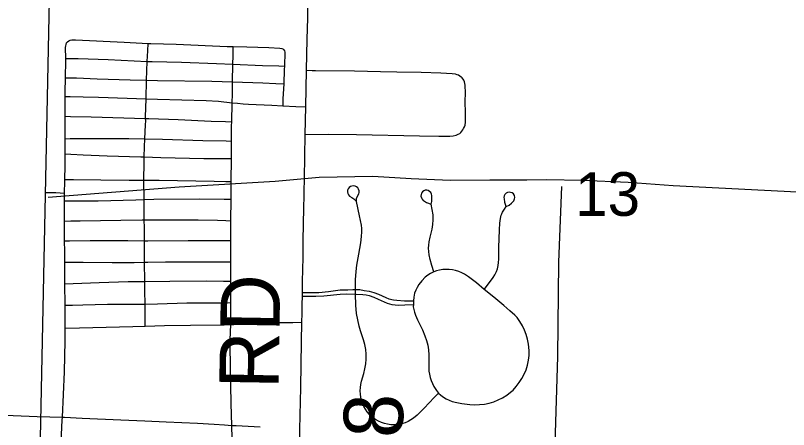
# Model space of a CAD drawing. Extents: x -59 to 43, y 0 to 22.
# Drawn here: x 24.177 to 24.918, y 18.594 to 18.99 of the extents above; entities that cross this region are included whole.
import ezdxf

# ---------------------------------------------------------------- set-up
doc = ezdxf.new("R2010")
doc.units = 0
for name, color, linetype in [('Default', 7, 'Continuous'), ('GM_X_City_Street', 7, 'Continuous'), ('GM_X_Minor_River', 7, 'Continuous'), ('GM_X_Section', 7, 'Continuous'), ('GM_X_Section_Text', 7, 'Continuous'), ('GM_X_Township_Road', 7, 'Continuous'), ('GM_X_Township_Road_Text', 7, 'Continuous')]:
    doc.layers.add(name, color=color, linetype=linetype)

msp = doc.modelspace()

# ---------------------------------------------------------------- linework, layer by layer
at = {"layer": 'Default'}
msp.add_lwpolyline([(23.51667, 19.36712), (23.51667, 18.36457), (24.19635, 18.35229), (24.21701, 19.34715)], close=True, dxfattribs=at)
at = {"layer": 'GM_X_City_Street'}
for p, q in [((24.50302, 18.72348), (24.50306, 18.72775)), ((24.55855, 18.717), (24.55845, 18.71346))]:
    msp.add_line(p, q, dxfattribs=at)
for points in [[(24.45614, 18.93773), (24.46159, 18.93762), (24.46471, 18.93756), (24.5021, 18.93711), (24.52702, 18.93654), (24.54259, 18.93626), (24.56597, 18.93586), (24.58467, 18.93531), (24.59555, 18.93469), (24.59863, 18.93429), (24.60013, 18.93389), (24.60157, 18.93334), (24.60292, 18.93257), (24.60416, 18.93162), (24.60525, 18.93051)], [(24.60285, 18.87732), (24.60401, 18.87834), (24.60505, 18.87947), (24.60592, 18.88073), (24.60659, 18.88211), (24.60738, 18.8835), (24.60812, 18.88523), (24.60836, 18.88807), (24.60836, 18.89288), (24.60836, 18.89831), (24.60823, 18.90657), (24.60836, 18.91741), (24.60823, 18.92202), (24.60813, 18.92355), (24.60789, 18.92506), (24.60761, 18.92676), (24.60686, 18.92824), (24.60525, 18.93051)], [(24.45481, 18.87638), (24.47765, 18.87661), (24.50393, 18.87612), (24.56419, 18.87512), (24.58273, 18.87471), (24.59355, 18.87464), (24.59662, 18.87484), (24.59961, 18.8756), (24.60134, 18.87646), (24.60285, 18.87732)], [(24.50306, 18.72775), (24.50309, 18.73252), (24.50312, 18.73717), (24.50365, 18.74489), (24.50436, 18.75103), (24.50638, 18.76167), (24.50827, 18.77234), (24.50894, 18.77849), (24.50922, 18.78312), (24.50908, 18.78622), (24.50865, 18.78928), (24.50673, 18.79836), (24.50399, 18.81203), (24.50392, 18.81358), (24.50411, 18.8151), (24.5046, 18.81656), (24.50608, 18.81929), (24.50655, 18.82075), (24.50655, 18.82229), (24.50607, 18.82375), (24.50522, 18.82505), (24.50409, 18.82609), (24.50269, 18.82675), (24.50117, 18.82702), (24.49962, 18.82689), (24.49817, 18.82637), (24.49693, 18.82547), (24.49598, 18.82424), (24.49541, 18.8228), (24.49528, 18.82127), (24.49562, 18.81979), (24.49639, 18.81845), (24.49744, 18.8173), (24.49968, 18.81607), (24.50145, 18.81476), (24.50269, 18.81336), (24.50359, 18.81238)], [(24.57806, 18.7448), (24.57628, 18.75069), (24.57451, 18.7566), (24.57361, 18.76115), (24.57323, 18.76421), (24.57311, 18.76729), (24.57326, 18.77036), (24.5736, 18.77343), (24.57454, 18.77797), (24.57633, 18.78547), (24.57709, 18.79004), (24.57753, 18.79465), (24.57752, 18.79928), (24.57556, 18.80969), (24.57608, 18.81221), (24.57631, 18.81579), (24.57623, 18.81777), (24.57579, 18.81926), (24.57507, 18.82063), (24.57406, 18.82179), (24.57279, 18.82262), (24.57132, 18.82301), (24.56981, 18.82295), (24.56838, 18.82241), (24.56717, 18.82147), (24.56628, 18.82021), (24.56579, 18.81875), (24.56574, 18.81722), (24.56611, 18.81573), (24.56683, 18.81436), (24.56785, 18.8132), (24.56906, 18.81226), (24.57119, 18.81111), (24.57541, 18.80964)], [(24.62643, 18.72789), (24.62937, 18.73187), (24.63492, 18.7394), (24.63653, 18.74199), (24.63825, 18.74496), (24.63911, 18.74755), (24.63985, 18.75063), (24.6401, 18.75371), (24.64023, 18.75694), (24.6405, 18.76787), (24.64083, 18.78503), (24.6412, 18.79126), (24.64183, 18.7959), (24.64266, 18.7989), (24.64325, 18.80034), (24.64395, 18.80173), (24.64574, 18.80461), (24.64752, 18.80728), (24.65012, 18.80869), (24.65257, 18.81065), (24.65384, 18.8117), (24.65486, 18.8128), (24.65549, 18.81454), (24.65557, 18.81607), (24.6554, 18.81798), (24.65447, 18.81954), (24.65307, 18.82044), (24.65167, 18.82086), (24.65012, 18.82107), (24.64859, 18.82079), (24.64723, 18.82006), (24.64617, 18.81895), (24.64556, 18.8176), (24.64526, 18.81607), (24.64531, 18.8145), (24.64589, 18.81139), (24.64718, 18.80749)], [(24.57806, 18.7448), (24.57485, 18.74326), (24.57228, 18.74152), (24.56991, 18.7395), (24.5667, 18.73612), (24.56381, 18.73246), (24.5621, 18.72986), (24.56068, 18.7271), (24.55967, 18.72417), (24.55884, 18.7205), (24.55855, 18.717)], [(24.62643, 18.72789), (24.61882, 18.73414), (24.61141, 18.73979), (24.60755, 18.74242), (24.60482, 18.74389), (24.60195, 18.74509), (24.59899, 18.74603), (24.59595, 18.74667), (24.59286, 18.74702), (24.58975, 18.74709), (24.58665, 18.74688), (24.58357, 18.74641), (24.58055, 18.74567), (24.57806, 18.7448)], [(24.45219, 18.72137), (24.46021, 18.72134), (24.4649, 18.72132), (24.47269, 18.72175), (24.48822, 18.72341), (24.49445, 18.72367), (24.50302, 18.72348)], [(24.45225, 18.72501), (24.45985, 18.72501), (24.46807, 18.72502), (24.47711, 18.72584), (24.4883, 18.72733), (24.49554, 18.7275), (24.50064, 18.72767), (24.50306, 18.72775)], [(24.50302, 18.72348), (24.50382, 18.72346), (24.51006, 18.72306), (24.51315, 18.72266), (24.5162, 18.722), (24.52064, 18.72056), (24.5249, 18.71862), (24.53053, 18.71589), (24.53345, 18.71476), (24.53793, 18.7135), (24.54101, 18.71306), (24.54413, 18.71295), (24.55038, 18.71317), (24.55845, 18.71346)], [(24.58267, 18.62863), (24.5785, 18.62425), (24.56888, 18.61413), (24.56227, 18.60757), (24.55873, 18.60455), (24.55617, 18.60281), (24.55341, 18.60139), (24.55053, 18.60023), (24.54609, 18.59884), (24.54305, 18.59823), (24.53996, 18.59801), (24.53686, 18.59822), (24.5338, 18.59872), (24.53079, 18.59948), (24.52785, 18.60048), (24.52501, 18.60173), (24.52229, 18.60322), (24.51978, 18.60503), (24.51636, 18.60819), (24.51433, 18.61054), (24.51256, 18.61308), (24.51103, 18.61579), (24.50978, 18.61863), (24.50881, 18.62157), (24.50812, 18.6246), (24.50771, 18.62767), (24.50756, 18.63078), (24.50768, 18.63388), (24.50806, 18.63696), (24.50869, 18.63999), (24.51097, 18.64741), (24.51208, 18.65193), (24.51285, 18.65652), (24.51325, 18.66115), (24.51323, 18.66581), (24.51286, 18.67045), (24.51205, 18.67503), (24.51081, 18.67952), (24.50778, 18.68832), (24.50653, 18.6928), (24.50514, 18.69884), (24.50406, 18.70495), (24.50322, 18.71267), (24.50302, 18.72348)], [(24.50306, 18.72775), (24.50705, 18.72767), (24.51146, 18.727), (24.51606, 18.72624), (24.52056, 18.72501), (24.52492, 18.72334), (24.532, 18.72008), (24.53492, 18.71901), (24.53945, 18.71794), (24.54253, 18.71754), (24.54999, 18.71683), (24.55855, 18.717)], [(24.58267, 18.62863), (24.58482, 18.62646), (24.58726, 18.62454), (24.58992, 18.62294), (24.59275, 18.62165), (24.59568, 18.62063), (24.6002, 18.61947), (24.60479, 18.61868), (24.6125, 18.6177), (24.61716, 18.61745), (24.62182, 18.61753), (24.62647, 18.61793), (24.63104, 18.6188), (24.63549, 18.62018), (24.63978, 18.62203), (24.64391, 18.62419), (24.6479, 18.6266), (24.65165, 18.62937), (24.65392, 18.63149), (24.65699, 18.63499), (24.65978, 18.63873), (24.66234, 18.64263), (24.66459, 18.64671), (24.66645, 18.65099), (24.66787, 18.65542), (24.66882, 18.65999), (24.66928, 18.66463), (24.66927, 18.66929), (24.66869, 18.67548), (24.66793, 18.68008), (24.66667, 18.68457), (24.66502, 18.68893), (24.66298, 18.69312), (24.66055, 18.69709), (24.65781, 18.70087), (24.65573, 18.70317), (24.65104, 18.70725), (24.64518, 18.71235), (24.63564, 18.72033), (24.62643, 18.72789)], [(24.55845, 18.71346), (24.55839, 18.71124), (24.55958, 18.70612), (24.56054, 18.70318), (24.56231, 18.69886), (24.56714, 18.68911), (24.56957, 18.68339), (24.57109, 18.67897), (24.57226, 18.67447), (24.57302, 18.66987), (24.57334, 18.66522), (24.57317, 18.65434), (24.57339, 18.64968), (24.57382, 18.64661), (24.57453, 18.64358), (24.5755, 18.64063), (24.57672, 18.63777), (24.57817, 18.63502), (24.5807, 18.6311), (24.58267, 18.62863)], [(24.12929, 18.60491), (24.13438, 18.60677), (24.1372, 18.60746), (24.1396, 18.60768), (24.14328, 18.60776), (24.15755, 18.60742), (24.17497, 18.60705), (24.19053, 18.60653), (24.1982, 18.60631)]]:
    msp.add_lwpolyline(points, dxfattribs=at)
at = {"layer": 'GM_X_Minor_River'}
for points in [[(24.20849, 18.81635), (24.33425, 18.82615), (24.42616, 18.83164), (24.46835, 18.83541), (24.51958, 18.83635), (24.55634, 18.83414), (24.59387, 18.83268), (24.63181, 18.83272), (24.66709, 18.83282), (24.68644, 18.83322), (24.71982, 18.83259), (24.76417, 18.83062), (24.80736, 18.82753), (24.89491, 18.82285), (24.97601, 18.81867), (25.02985, 18.8169), (25.09316, 18.81419), (25.14655, 18.80901), (25.1693, 18.8082)], [(24.70035, 18.8265), (24.69746, 18.75395), (24.6965, 18.66351), (24.69414, 18.57955)]]:
    msp.add_lwpolyline(points, dxfattribs=at)
at = {"layer": 'GM_X_Section'}
msp.add_lwpolyline([(24.21701, 19.34715), (25.1966, 19.31798), (25.19616, 19.28425), (25.1906, 18.3142), (24.19635, 18.35229)], close=True, dxfattribs=at)
at = {"layer": 'GM_X_Township_Road'}
for p, q in [((24.45614, 18.93773), (24.45678, 18.96768)), ((24.30281, 18.92824), (24.30358, 18.94625)), ((24.3853, 18.92671), (24.38559, 18.94372)), ((24.45538, 18.90269), (24.45614, 18.93773)), ((24.30235, 18.91045), (24.30281, 18.92824)), ((24.38446, 18.88843), (24.3849, 18.90669)), ((24.45481, 18.87638), (24.45538, 18.90269)), ((24.38397, 18.83111), (24.38415, 18.85328)), ((24.30058, 18.81402), (24.30032, 18.83258)), ((24.38383, 18.81435), (24.38397, 18.83111)), ((24.38369, 18.79361), (24.38383, 18.81435)), ((24.22441, 18.77452), (24.22431, 18.7934)), ((24.30105, 18.75399), (24.30087, 18.77457)), ((24.3012, 18.7356), (24.30105, 18.75399)), ((24.22479, 18.71277), (24.22474, 18.73325)), ((24.38362, 18.7152), (24.38359, 18.73581)), ((24.45219, 18.72137), (24.45225, 18.72501)), ((24.1982, 18.60631), (24.22225, 18.60563))]:
    msp.add_line(p, q, dxfattribs=at)
for points in [[(24.45678, 18.96768), (24.45722, 18.9876), (24.45775, 19.01167), (24.45839, 19.03959), (24.45899, 19.06286), (24.45942, 19.0797)], [(24.22541, 18.94915), (24.2253, 18.9596), (24.22547, 18.96111), (24.22572, 18.96259), (24.2263, 18.96398), (24.22712, 18.96514), (24.22827, 18.96588), (24.22966, 18.96654), (24.23114, 18.96679), (24.23494, 18.96682), (24.28151, 18.96463), (24.30433, 18.96349)], [(24.30358, 18.94625), (24.30402, 18.9564), (24.30433, 18.96349)], [(24.30433, 18.96349), (24.30695, 18.96336), (24.33118, 18.96265), (24.38024, 18.96054), (24.38588, 18.96041)], [(24.38559, 18.94372), (24.38573, 18.9515), (24.38588, 18.96041)], [(24.38588, 18.96041), (24.39888, 18.96011), (24.42, 18.95959), (24.43058, 18.95904), (24.43242, 18.95872), (24.43357, 18.95824), (24.43451, 18.9575), (24.43507, 18.95644), (24.43524, 18.95522), (24.43493, 18.94179)], [(24.22521, 18.9306), (24.22543, 18.94715), (24.22541, 18.94915)], [(24.22541, 18.94915), (24.23178, 18.94905), (24.23738, 18.94896), (24.266, 18.94795), (24.30358, 18.94625)], [(24.30358, 18.94625), (24.30829, 18.94604), (24.3363, 18.94541), (24.3699, 18.94442), (24.38559, 18.94372)], [(24.38559, 18.94372), (24.41406, 18.94244), (24.42962, 18.94196), (24.43493, 18.94179)], [(24.43493, 18.94179), (24.43485, 18.93842), (24.43423, 18.92494)], [(24.22502, 18.91267), (24.22502, 18.91666), (24.22521, 18.9306)], [(24.22521, 18.9306), (24.22887, 18.93059), (24.23569, 18.93055), (24.25554, 18.92971), (24.28719, 18.92874), (24.30281, 18.92824)], [(24.30281, 18.92824), (24.31325, 18.92791), (24.36538, 18.92731), (24.3853, 18.92671)], [(24.3849, 18.90669), (24.38509, 18.91487), (24.3853, 18.92671)], [(24.3853, 18.92671), (24.4144, 18.92583), (24.42681, 18.92527), (24.43423, 18.92494)], [(24.43423, 18.92494), (24.43357, 18.91048), (24.43327, 18.90379)], [(24.22489, 18.89373), (24.225, 18.89986), (24.22502, 18.91267)], [(24.22502, 18.91267), (24.22956, 18.91262), (24.242, 18.91247), (24.25692, 18.91191), (24.30235, 18.91045)], [(24.30199, 18.89157), (24.3019, 18.89305), (24.30235, 18.91045)], [(24.30235, 18.91045), (24.3135, 18.91009), (24.36014, 18.90886), (24.37193, 18.9082), (24.3849, 18.90669)], [(24.3849, 18.90669), (24.38985, 18.90612), (24.39543, 18.90568), (24.40039, 18.90541), (24.42276, 18.90431), (24.43327, 18.90379)], [(24.43327, 18.90379), (24.44575, 18.90317), (24.45538, 18.90269)], [(24.22497, 18.87227), (24.22476, 18.8868), (24.22489, 18.89373)], [(24.22489, 18.89373), (24.2299, 18.8936), (24.2498, 18.89309), (24.30199, 18.89157)], [(24.30124, 18.87227), (24.30179, 18.88561), (24.30212, 18.88933), (24.30199, 18.89157)], [(24.30199, 18.89157), (24.30515, 18.89148), (24.33313, 18.89051), (24.36482, 18.88905), (24.3785, 18.88862), (24.38446, 18.88843)], [(24.38427, 18.87003), (24.38437, 18.88445), (24.38446, 18.88843)], [(24.22493, 18.85787), (24.22499, 18.87062), (24.22497, 18.87227)], [(24.22497, 18.87227), (24.22984, 18.8723), (24.25595, 18.87246), (24.28579, 18.87259), (24.30124, 18.87227)], [(24.30068, 18.85487), (24.30092, 18.86451), (24.30124, 18.87227)], [(24.30124, 18.87227), (24.31812, 18.87192), (24.35665, 18.87061), (24.37902, 18.87013), (24.38427, 18.87003)], [(24.38415, 18.85328), (24.38421, 18.86086), (24.38427, 18.87003)], [(24.45225, 18.72501), (24.45241, 18.73539), (24.45276, 18.75836), (24.45276, 18.76338), (24.45282, 18.77103), (24.45334, 18.79414), (24.45352, 18.80219), (24.4538, 18.82149), (24.45417, 18.83427), (24.45481, 18.87638)], [(24.22461, 18.83332), (24.22487, 18.84635), (24.22493, 18.85787)], [(24.22493, 18.85787), (24.23039, 18.85749), (24.24216, 18.85669), (24.26513, 18.85577), (24.29741, 18.85497), (24.30068, 18.85487)], [(24.30032, 18.83258), (24.30055, 18.8496), (24.30068, 18.85487)], [(24.30068, 18.85487), (24.31666, 18.85436), (24.35764, 18.85316), (24.37441, 18.85318), (24.37566, 18.85319), (24.38415, 18.85328)], [(24.22434, 18.82017), (24.22458, 18.83142), (24.22461, 18.83332)], [(24.22461, 18.83332), (24.23291, 18.83323), (24.25899, 18.83294), (24.2863, 18.83267), (24.30032, 18.83258)], [(24.30032, 18.83258), (24.31486, 18.83248), (24.36763, 18.83147), (24.37879, 18.83122), (24.38397, 18.83111)], [(24.20528, 18.8206), (24.21466, 18.82069), (24.21591, 18.82062), (24.22434, 18.82017)], [(24.22427, 18.81262), (24.22426, 18.81649), (24.22434, 18.82017)], [(24.22427, 18.81262), (24.22966, 18.81266), (24.2564, 18.81284), (24.29247, 18.81382), (24.30058, 18.81402)], [(24.22431, 18.7934), (24.2243, 18.79782), (24.22427, 18.81262)], [(24.30058, 18.81402), (24.30988, 18.81427), (24.35405, 18.81451), (24.37707, 18.81438), (24.38383, 18.81435)], [(24.30074, 18.79457), (24.30072, 18.80362), (24.30058, 18.81402)], [(24.22431, 18.7934), (24.23045, 18.79346), (24.23915, 18.79354), (24.27829, 18.79431), (24.29879, 18.79456), (24.30074, 18.79457)], [(24.30074, 18.79457), (24.3224, 18.79465), (24.35223, 18.79438), (24.37086, 18.79413), (24.37893, 18.7938), (24.38369, 18.79361)], [(24.30087, 18.77457), (24.30076, 18.78683), (24.30074, 18.79457)], [(24.38358, 18.77488), (24.38368, 18.79193), (24.38369, 18.79361)], [(24.22441, 18.77452), (24.22916, 18.77455), (24.24901, 18.77468), (24.285, 18.77468), (24.30087, 18.77457)], [(24.22461, 18.75401), (24.22446, 18.76421), (24.22441, 18.77452)], [(24.30087, 18.77457), (24.30423, 18.77454), (24.3427, 18.77459), (24.37682, 18.77483), (24.38358, 18.77488)], [(24.38357, 18.75444), (24.38353, 18.76833), (24.38358, 18.77488)], [(24.22474, 18.73325), (24.22471, 18.74804), (24.22461, 18.75401)], [(24.22461, 18.75401), (24.23158, 18.75399), (24.24214, 18.75397), (24.27006, 18.75365), (24.29116, 18.75377), (24.30105, 18.75399)], [(24.30105, 18.75399), (24.30419, 18.75407), (24.32094, 18.75435), (24.3619, 18.75435), (24.37804, 18.75442), (24.38357, 18.75444)], [(24.38359, 18.73581), (24.38358, 18.74721), (24.38357, 18.75444)], [(24.22474, 18.73325), (24.2327, 18.73354), (24.2575, 18.73444), (24.28541, 18.73543), (24.3012, 18.7356)], [(24.3012, 18.7356), (24.32512, 18.73585), (24.35987, 18.7361), (24.37662, 18.7359), (24.38359, 18.73581)], [(24.30141, 18.71389), (24.30128, 18.72654), (24.3012, 18.7356)], [(24.30141, 18.71389), (24.31335, 18.71411), (24.34136, 18.7149), (24.37684, 18.71515), (24.38362, 18.7152)], [(24.38364, 18.69421), (24.38363, 18.70064), (24.38362, 18.7152)], [(24.4519, 18.70578), (24.45207, 18.7133), (24.45219, 18.72137)], [(24.22479, 18.71277), (24.23183, 18.71294), (24.24178, 18.71317), (24.26543, 18.71378), (24.27726, 18.71367), (24.28846, 18.71365), (24.30141, 18.71389)], [(24.22494, 18.69083), (24.22479, 18.71195), (24.22479, 18.71277)], [(24.30164, 18.69271), (24.30159, 18.69733), (24.30141, 18.71389)], [(24.4517, 18.69637), (24.45188, 18.70484), (24.4519, 18.70578)], [(24.22494, 18.69083), (24.23862, 18.69118), (24.28961, 18.69234), (24.30164, 18.69271)], [(24.30164, 18.69271), (24.32007, 18.69327), (24.34493, 18.69359), (24.37728, 18.69397), (24.38364, 18.69421)], [(24.38455, 18.59767), (24.38394, 18.61876), (24.38358, 18.63618), (24.38339, 18.65609), (24.38295, 18.67225), (24.38285, 18.67973), (24.38364, 18.69421)], [(24.38364, 18.69421), (24.38662, 18.69432), (24.3978, 18.69501), (24.42447, 18.69626), (24.44311, 18.69634), (24.4517, 18.69637)], [(24.44906, 18.55561), (24.44987, 18.59362), (24.4506, 18.63403), (24.4513, 18.67755), (24.4517, 18.69637)], [(24.22225, 18.60563), (24.22336, 18.62735), (24.2242, 18.64906), (24.22494, 18.67866), (24.22494, 18.69083)], [(24.22113, 18.57934), (24.22152, 18.58889), (24.22209, 18.60254), (24.22225, 18.60563)], [(24.22225, 18.60563), (24.22433, 18.60557), (24.24107, 18.6047), (24.27832, 18.60296), (24.30128, 18.60186), (24.32176, 18.60091), (24.35156, 18.59968), (24.36768, 18.59884), (24.37759, 18.59812), (24.38455, 18.59767)], [(24.38688, 18.53182), (24.38641, 18.53538), (24.38542, 18.5578), (24.38479, 18.58519), (24.38455, 18.59767)], [(24.38455, 18.59767), (24.38876, 18.59741), (24.41174, 18.59638)]]:
    msp.add_lwpolyline(points, dxfattribs=at)

# ---------------------------------------------------------------- texts
at = {"layer": 'GM_X_Section_Text'}
msp.add_text('13', height=0.041856, rotation=0.00001, dxfattribs=at).set_placement((24.71339, 18.79832))
at = {"layer": 'GM_X_Township_Road_Text'}
for s, rotation, p in [('RD', 89.01169, (24.42924, 18.63217)), ('T-98', 88.95303, (24.54616, 18.4713))]:
    msp.add_text(s, height=0.056818, rotation=rotation, dxfattribs=at).set_placement(p)

doc.saveas('drawing.dxf')
